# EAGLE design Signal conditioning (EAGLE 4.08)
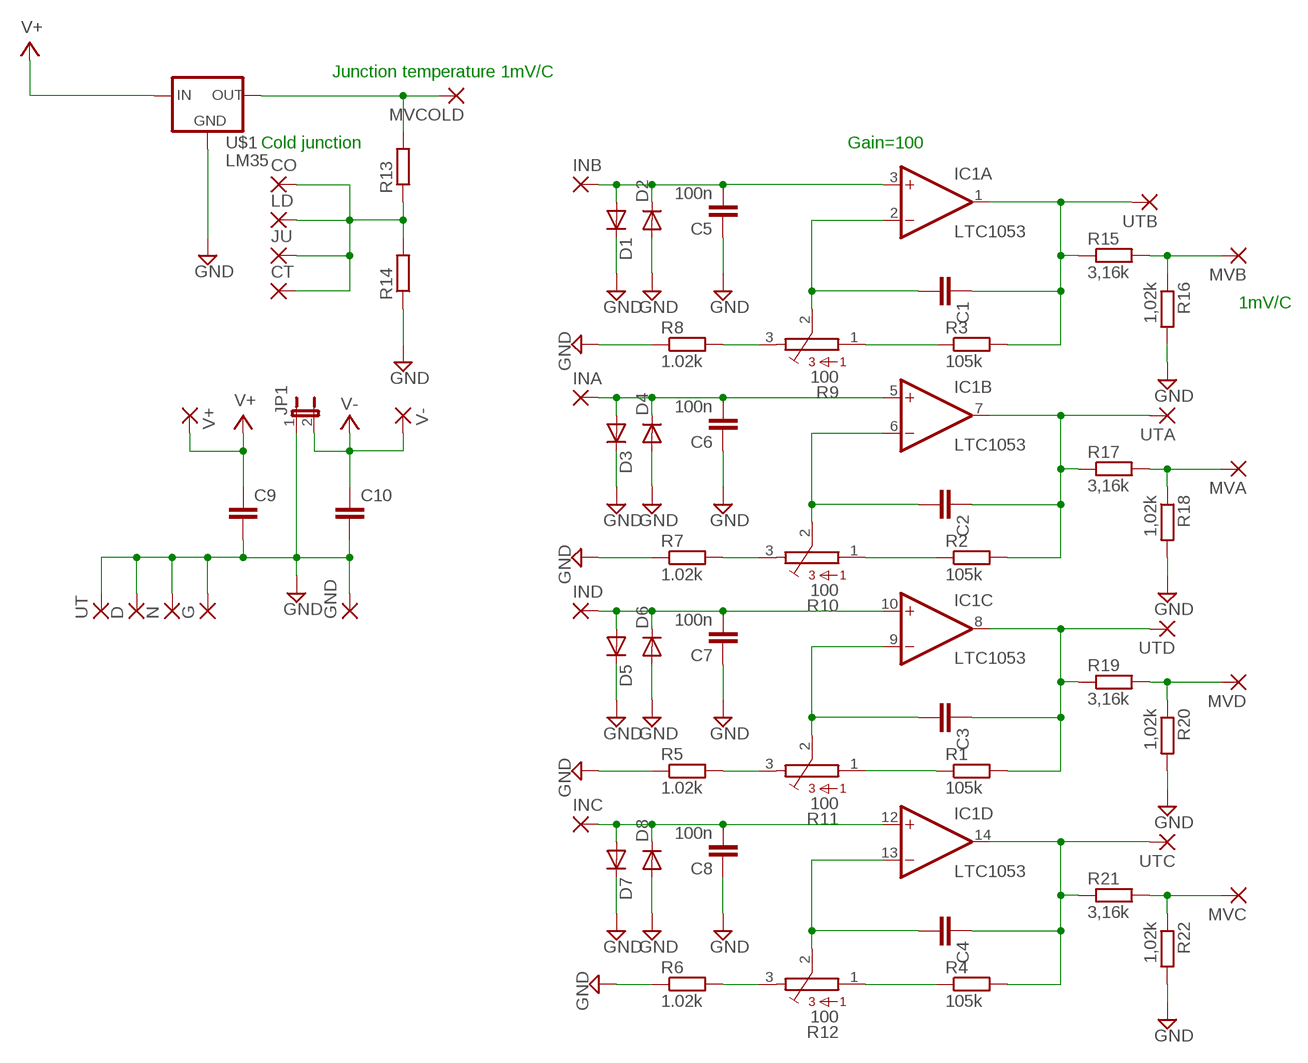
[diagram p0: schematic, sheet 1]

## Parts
C1  C-EU050-025X075  [C050-025X075]
C2  C-EU050-025X075  [C050-025X075]
C3  C-EU050-025X075  [C050-025X075]
C4  C-EU050-025X075  [C050-025X075]
C5  100n  C-EU025-030X050  [C025-030X050]
C6  100n  C-EU025-030X050  [C025-030X050]
C7  100n  C-EU025-030X050  [C025-030X050]
C8  100n  C-EU025-030X050  [C025-030X050]
C9  C-EU025-050X050  [C025-050X050]
C10  C-EU025-050X050  [C025-050X050]
CO  2,54/1,0  [2,54/1,0]
CT  2,54/1,0  [2,54/1,0]
D  2,15/1,0  [2,15/1,0]
D1  DIODE-D-2.5  [D-2.5]
D2  DIODE-D-2.5  [D-2.5]
D3  DIODE-D-2.5  [D-2.5]
D4  DIODE-D-2.5  [D-2.5]
D5  DIODE-D-2.5  [D-2.5]
D6  DIODE-D-2.5  [D-2.5]
D7  DIODE-D-2.5  [D-2.5]
D8  DIODE-D-2.5  [D-2.5]
G  2,15/1,0  [2,15/1,0]
GND  2,15/1,0  [2,15/1,0]
IC1  LTC1053  LM324N  [DIL14]
INA  2,54/1,0  [2,54/1,0]
INB  2,54/1,0  [2,54/1,0]
INC  2,54/1,0  [2,54/1,0]
IND  2,54/1,0  [2,54/1,0]
JP1  JP1E  [JP1]
JU  2,54/1,0  [2,54/1,0]
LD  2,54/1,0  [2,54/1,0]
MVA  2,54/1,0  [2,54/1,0]
MVB  2,54/1,0  [2,54/1,0]
MVC  2,54/1,0  [2,54/1,0]
MVCOLD  2,54/1,0  [2,54/1,0]
MVD  2,54/1,0  [2,54/1,0]
N  2,15/1,0  [2,15/1,0]
R1  105k  R-EU_0207/7  [0207/7]
R2  105k  R-EU_0207/7  [0207/7]
R3  105k  R-EU_0207/7  [0207/7]
R4  105k  R-EU_0207/7  [0207/7]
R5  1.02k  R-EU_0207/7  [0207/7]
R6  1.02k  R-EU_0207/7  [0207/7]
R7  1.02k  R-EU_0207/7  [0207/7]
R8  1.02k  R-EU_0207/7  [0207/7]
R9  100  B64W  [B64W]
R10  100  B64W  [B64W]
R11  100  B64W  [B64W]
R12  100  B64W  [B64W]
R13  R-EU_0207/7  [0207/7]
R14  R-EU_0207/7  [0207/7]
R15  3,16k  R-EU_0207/2V  [0207/2V]
R16  1,02k  R-EU_0207/2V  [0207/2V]
R17  3,16k  R-EU_0207/2V  [0207/2V]
R18  1,02k  R-EU_0207/2V  [0207/2V]
R19  3,16k  R-EU_0207/2V  [0207/2V]
R20  1,02k  R-EU_0207/2V  [0207/2V]
R21  3,16k  R-EU_0207/2V  [0207/2V]
R22  1,02k  R-EU_0207/2V  [0207/2V]
U$1  LM35  [TO92]
UT  2,15/1,0  [2,15/1,0]
UTA  2,54/1,0  [2,54/1,0]
UTB  2,54/1,0  [2,54/1,0]
UTC  2,54/1,0  [2,54/1,0]
UTD  2,54/1,0  [2,54/1,0]
V+  2,15/1,0  [2,15/1,0]
V-  2,15/1,0  [2,15/1,0]

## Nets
GND: C5.1 C6.1 C7.1 C8.1 C9.2 C10.2 D1.C D2.A D3.C D4.A D5.C D6.A D7.C D8.A D.1(P) G.1(P) GND.1(P) JP1.1 N.1(P) R5.1 R6.1 R7.1 R8.1 R14.1 R16.2 R18.2 R20.2 R22.2 U$1.3(GND) UT.1(P)
N$1: R8.2 R9.3
N$2: C2.2 IC1.6(B:-IN) R10.2
N$3: C1.1 IC1.1(A:OUT) R3.2 R15.1 UTB.1(P)
N$4: C5.2 D1.A D2.C IC1.3(A:+IN) INB.1(P)
N$5: R3.1 R9.1
N$6: R7.2 R10.3
N$7: MVCOLD.1(P) R13.2 U$1.2(OUT)
N$8: C2.1 IC1.7(B:OUT) R2.2 R17.1 UTA.1(P)
N$9: C1.2 IC1.2(A:-IN) R9.2
N$10: R2.1 R10.1
N$11: CO.1(P) CT.1(P) JU.1(P) LD.1(P) R13.1 R14.2
N$12: C3.2 IC1.9(C:-IN) R11.2
N$14: R1.1 R11.1
N$15: R5.2 R11.3
N$16: MVC.1(P) R21.2 R22.1
N$17: R6.2 R12.3
N$18: R4.1 R12.1
N$19: C4.2 IC1.13(D:-IN) R12.2
N$21: C3.1 IC1.8(C:OUT) R1.2 R19.1 UTD.1(P)
N$23: C4.1 IC1.14(D:OUT) R4.2 R21.1 UTC.1(P)
N$24: MVD.1(P) R19.2 R20.1
N$25: C8.2 D7.A D8.C IC1.12(D:+IN) INC.1(P)
N$26: C7.2 D5.A D6.C IC1.10(C:+IN) IND.1(P)
N$27: C6.2 D3.A D4.C IC1.5(B:+IN) INA.1(P)
PAD20C: MVA.1(P) R17.2 R18.1
PAD21C: MVB.1(P) R15.2 R16.1
V+: C9.1 U$1.1(IN) V+.1(P)
V-: C10.1 JP1.2 V-.1(P)

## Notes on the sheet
- Junction temperature 1mV/C
- Cold junction | Gain=100
- 1mV/C

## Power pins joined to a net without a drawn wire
V+: IC1.4(P:V+)
V-: IC1.11(P:V-)

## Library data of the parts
C1-C10 = rcl:C-EU: CAPACITOR, European symbol
CO CT INA INB INC IND JU LD MVA MVB MVC MVCOLD MVD UTA UTB UTC UTD = wirepad:2,54/1,0: THROUGH-HOLE PAD
D G GND N UT V+ V- = wirepad:2,15/1,0: THROUGH-HOLE PAD
D1-D8 = diode:DIODE-: DIODE
IC1 = linear:LM324N: OP AMP
JP1 = jumper:JP1E: JUMPER
R1-R8 R13-R22 = rcl:R-EU_: RESISTOR, European symbol
R9-R12 = pot:B64W: POTENTIOMETER
U$1 = jurg:LM35

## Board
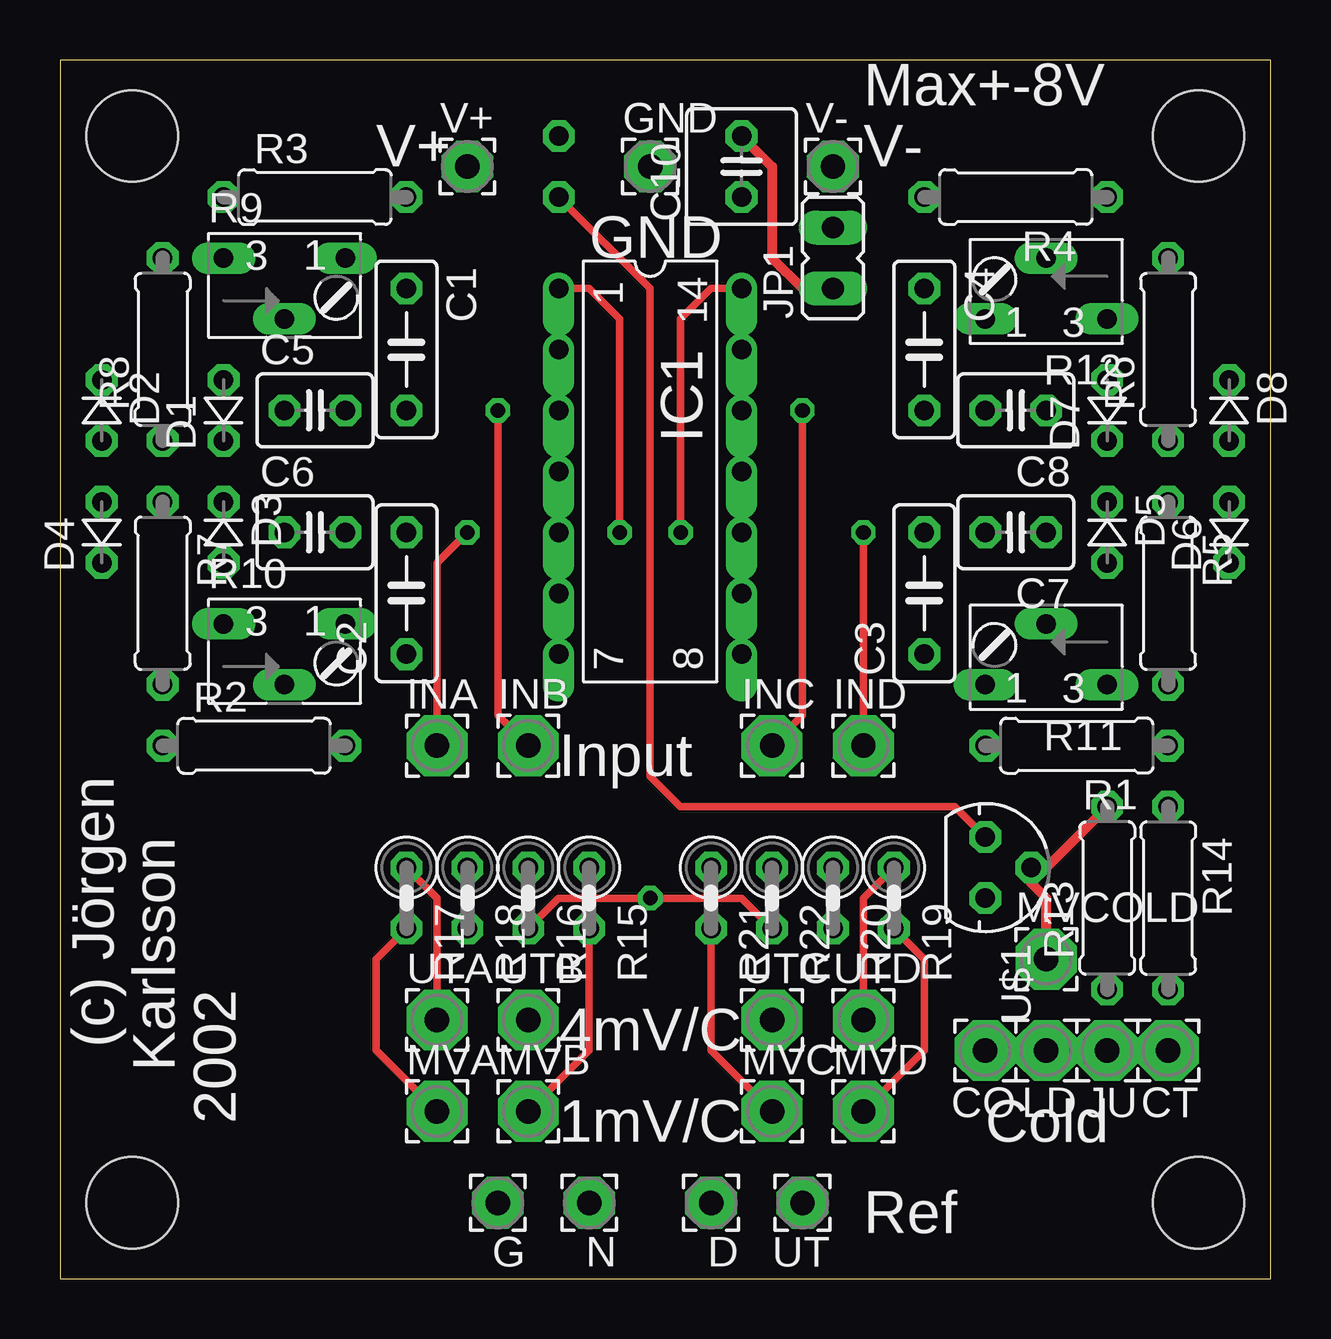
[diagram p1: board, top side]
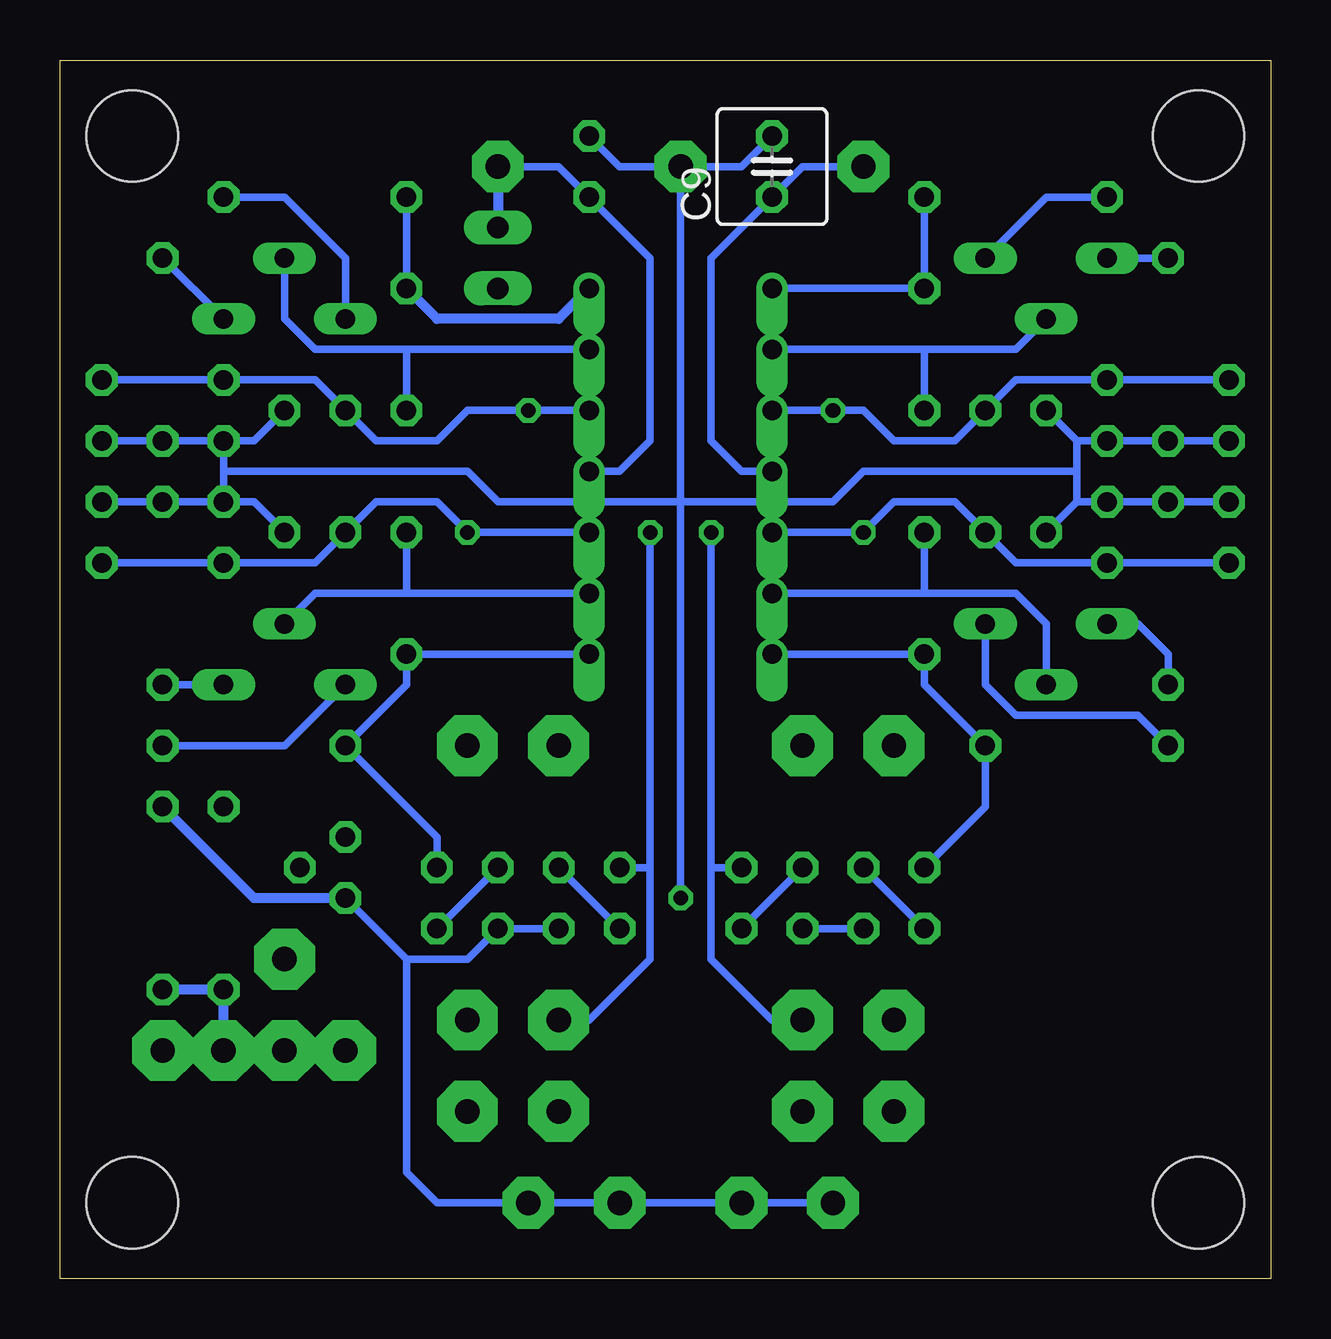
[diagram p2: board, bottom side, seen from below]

Size 50.47 x 50.79 mm. Coordinates in mm from the lower left corner, seen from the top.
Outline: 0,0 50.47,0 50.47,50.79 0,50.79 0,0
Copper layers used: Top, Bottom
Holes 3.81 mm at 3.01,47.62 47.46,47.62 3.01,3.17 47.46,3.17

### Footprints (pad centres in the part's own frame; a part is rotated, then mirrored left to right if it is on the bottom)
C050-025X075 = drill 0.813 octagon: 1 -2.54,0; 2 2.54,0
C025-030X050 = drill 0.813 octagon: 1 -1.27,0; 2 1.27,0
C025-050X050 = drill 0.813 octagon: 1 -1.27,0; 2 1.27,0
2,54/1,0 = drill 1.016 pad 2.54 octagon: 1 0,0
2,15/1,0 = drill 1.016 pad 2.159 octagon: 1 0,0
D-2.5 = drill 0.813 octagon: A 1.27,0; C -1.27,0
DIL14 = drill 0.813 offset: 1 -7.62,-3.81; 2 -5.08,-3.81; 3 -2.54,-3.81; 4 0,-3.81; 5 2.54,-3.81; 6 5.08,-3.81; 7 7.62,-3.81; 8 7.62,3.81; 9 5.08,3.81; 10 2.54,3.81; 11 0,3.81; 12 -2.54,3.81; 13 -5.08,3.81; 14 -7.62,3.81
JP1 = drill 0.914 long: 1 0,-1.27; 2 0,1.27
0207/7 = drill 0.813 octagon: 1 -3.81,0; 2 3.81,0
B64W = drill 0.813 long: 1 2.54,0; 2 0,-2.54; 3 -2.54,0
0207/2V = drill 0.813 octagon: 1 -1.27,0; 2 1.27,0
TO92 = drill 0.813 octagon: 1 -1.27,0; 2 0,1.905; 3 1.27,0

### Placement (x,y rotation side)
C1  14.44,38.73 270 top
C2  14.44,28.57 90 top
C3  36.03,28.57 90 top
C4  36.03,38.73 270 top
C5  10.63,36.19 0 top
C6  10.63,31.11 0 top
C7  39.84,31.11 180 top
C8  39.84,36.19 180 top
C9  20.79,46.35 90 bottom
C10  28.41,46.35 90 top
CO  38.57,9.52 180 top
CT  46.19,9.52 180 top
D  27.14,3.17 180 top
D1  6.82,36.19 90 top
D2  1.74,36.19 270 top
D3  6.82,31.11 270 top
D4  1.74,31.11 90 top
D5  43.65,31.11 270 top
D6  48.73,31.11 90 top
D7  43.65,36.19 90 top
D8  48.73,36.19 270 top
G  18.25,3.17 180 top
GND  24.6,46.35 0 top
IC1  24.6,33.65 270 top
INA  15.71,22.22 0 top
INB  19.52,22.22 0 top
INC  29.68,22.22 0 top
IND  33.49,22.22 0 top
JP1  32.22,42.54 0 top
JU  43.65,9.52 180 top
LD  41.11,9.52 180 top
MVA  15.71,6.98 0 top
MVB  19.52,6.98 0 top
MVC  29.68,6.98 0 top
MVCOLD  41.11,13.33 0 top
MVD  33.49,6.98 0 top
N  22.06,3.17 180 top
R1  42.38,22.22 180 top
R2  8.09,22.22 0 top
R3  10.63,45.08 0 top
R4  39.84,45.08 180 top
R5  46.19,28.57 270 top
R6  46.19,38.73 90 top
R7  4.28,28.57 270 top
R8  4.28,38.73 90 top
R9  9.36,42.54 0 top
R10  9.36,27.3 0 top
R11  41.11,24.76 180 top
R12  41.11,40 180 top
R13  43.65,15.87 90 top
R14  46.19,15.87 270 top
R15  22.06,15.87 270 top
R16  19.52,15.87 270 top
R17  14.44,15.87 270 top
R18  16.98,15.87 270 top
R19  34.76,15.87 270 top
R20  32.22,15.87 270 top
R21  27.14,15.87 270 top
R22  29.68,15.87 270 top
U$1  38.57,17.14 270 top
UT  30.95,3.17 180 top
UTA  15.71,10.79 0 top
UTB  19.52,10.79 0 top
UTC  29.68,10.79 0 top
UTD  33.49,10.79 0 top
V+  16.98,46.35 0 top
V-  32.22,46.35 0 top

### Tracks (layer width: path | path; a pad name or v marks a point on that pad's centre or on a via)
GND  (via drill 0.61 pad 0.61)
  Top 0.305: R16.2 20.79,15.87 v24.6,15.87 28.41,15.87 R22.2
  Top 0.406: JP1.1 30.95,41.27 29.68,42.54 29.68,46.35 C10.2
  Bottom 0.305: D4.A R7.1 D3.C 8.09,32.38 | D2.A R8.1 D1.C 8.09,34.92 | 8.09,34.92 C5.1 | 8.09,32.38 C6.1 | 8.09,33.65 8.09,32.38 | 8.09,33.65 8.09,34.92 | D8.A R6.1 D7.C | D6.A R5.1 D5.C | D5.C 42.38,32.38 C7.1 | D7.C 42.38,34.92 C8.1 | 43.65,33.65 D5.C | 43.65,33.65 D7.C | GND.1 22.06,46.35 C9.2 | GND.1 27.14,46.35 C10.2 | 24.6,32.38 GND.1 | G.1 N.1 D.1 UT.1 34.76,3.17 36.03,4.44 36.03,13.33 | 36.03,13.33 U$1.3 | 43.65,33.65 33.49,33.65 32.22,32.38 24.6,32.38 | 24.6,32.38 18.25,32.38 16.98,33.65 8.09,33.65 | R16.2 R18.2 | R22.2 R20.2 33.49,13.33 36.03,13.33 | v24.6,15.87 24.6,32.38
  Bottom 0.406: U$1.3 42.38,15.87 R14.1
N$1
  Bottom 0.305: R8.2 R9.3
N$2
  Bottom 0.305: 14.44,28.57 10.63,28.57 9.36,27.3 R10.2 | 14.44,28.57 IC1.6 | 14.44,28.57 C2.2
N$3  (via drill 0.61 pad 0.61)
  Top 0.305: v23.33,31.11 23.33,40 22.06,41.27 IC1.1
  Bottom 0.305: IC1.1 C1.1 R3.2 | UTB.1 20.79,10.79 23.33,13.33 23.33,17.14 | 23.33,17.14 v23.33,31.11 | 23.33,17.14 R15.1
N$4  (via drill 0.61 pad 0.61)
  Top 0.305: INB.1 18.25,23.49 v18.25,36.19
  Bottom 0.305: IC1.3 v18.25,36.19 16.98,36.19 15.71,34.92 13.17,34.92 C5.2 10.63,37.46 D1.A D2.C
N$5
  Bottom 0.305: R3.1 9.36,45.08 R9.1
N$6
  Bottom 0.305: R7.2 4.28,26.03 5.55,27.3 R10.3
N$7
  Top 0.406: MVCOLD.1 41.11,15.87 40.48,16.5 U$1.2 41.11,17.14 R13.2
N$8
  Top 0.305: UTA.1 15.71,15.87 R17.1
  Bottom 0.305: IC1.7 C2.1 14.44,24.76 R2.2 11.9,19.68 R17.1
N$9
  Bottom 0.305: 14.44,38.73 10.63,38.73 R9.2 | 14.44,38.73 IC1.2 | 14.44,38.73 C1.2
N$10
  Bottom 0.305: R10.1 11.9,24.76 10.63,23.49 5.55,23.49 R2.1
N$11
  Bottom 0.305: CT.1 JU.1 LD.1 CO.1
  Bottom 0.406: R14.2 R13.1 JU.1
N$12
  Bottom 0.305: IC1.9 36.03,28.57 | 36.03,28.57 39.84,28.57 R11.2 | 36.03,28.57 C3.2
N$14
  Bottom 0.305: R11.1 41.11,22.22 R1.1
N$15
  Bottom 0.305: R11.3 R5.2
N$16
  Top 0.305: MVC.1 27.14,9.52 R21.2
  Bottom 0.305: R21.2 R22.1
N$17
  Bottom 0.305: R12.3 R6.2
N$18
  Bottom 0.305: R4.1 41.11,45.08 38.57,42.54 R12.1
N$19
  Bottom 0.305: IC1.13 36.03,38.73 | 36.03,38.73 39.84,38.73 41.11,40 R12.2 | 36.03,38.73 C4.2
N$21
  Top 0.305: UTD.1 33.49,15.87 R19.1
  Bottom 0.305: IC1.8 C3.1 36.03,24.76 R1.2 34.76,18.41 R19.1
N$23  (via drill 0.61 pad 0.61)
  Top 0.305: IC1.14 27.14,41.27 25.87,40 v25.87,31.11
  Bottom 0.305: C4.1 R4.2 | 25.87,17.14 v25.87,31.11 | UTC.1 28.41,10.79 25.87,13.33 25.87,17.14 | 25.87,17.14 R21.1
  Bottom 0.406: IC1.14 29.68,40 34.76,40 C4.1
N$24
  Top 0.305: MVD.1 36.03,9.52 36.03,13.33 R19.2
  Bottom 0.305: R19.2 R20.1
N$25  (via drill 0.61 pad 0.61)
  Top 0.305: INC.1 30.95,23.49 v30.95,36.19
  Bottom 0.305: IC1.12 v30.95,36.19 33.49,36.19 34.76,34.92 37.3,34.92 C8.2 39.84,37.46 D7.A D8.C
N$26  (via drill 0.61 pad 0.61)
  Top 0.305: IND.1 v33.49,31.11
  Bottom 0.305: IC1.10 v33.49,31.11 34.76,32.38 37.3,32.38 C7.2 39.84,29.84 D5.A D6.C
N$27  (via drill 0.61 pad 0.61)
  Top 0.305: INA.1 15.71,29.84 v16.98,31.11
  Bottom 0.305: D4.C D3.A 10.63,29.84 C6.2 13.17,32.38 15.71,32.38 v16.98,31.11 IC1.5
PAD20C
  Top 0.305: MVA.1 13.17,9.52 13.17,13.33 R17.2
  Bottom 0.305: R17.2 R18.1
PAD21C
  Top 0.305: R15.2 22.06,9.52 MVB.1
  Bottom 0.305: R15.2 R16.1
V+
  Top 0.305: U$1.1 37.3,19.68 36.03,19.68 25.87,19.68 24.6,20.95 24.6,41.27 C9.1
  Bottom 0.305: V+.1 19.52,46.35 C9.1 23.33,42.54 23.33,34.92 22.06,33.65 IC1.4
V-
  Bottom 0.305: V-.1 29.68,46.35 C10.1 25.87,42.54 25.87,34.92 27.14,33.65 IC1.11
  Bottom 0.406: V-.1 JP1.2

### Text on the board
tPlace: Max+-8V | V+ | V- | GND | (c) Jörgen | Input | Karlsson | 2002 | 4mV/C | 1mV/C | Cold | Ref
